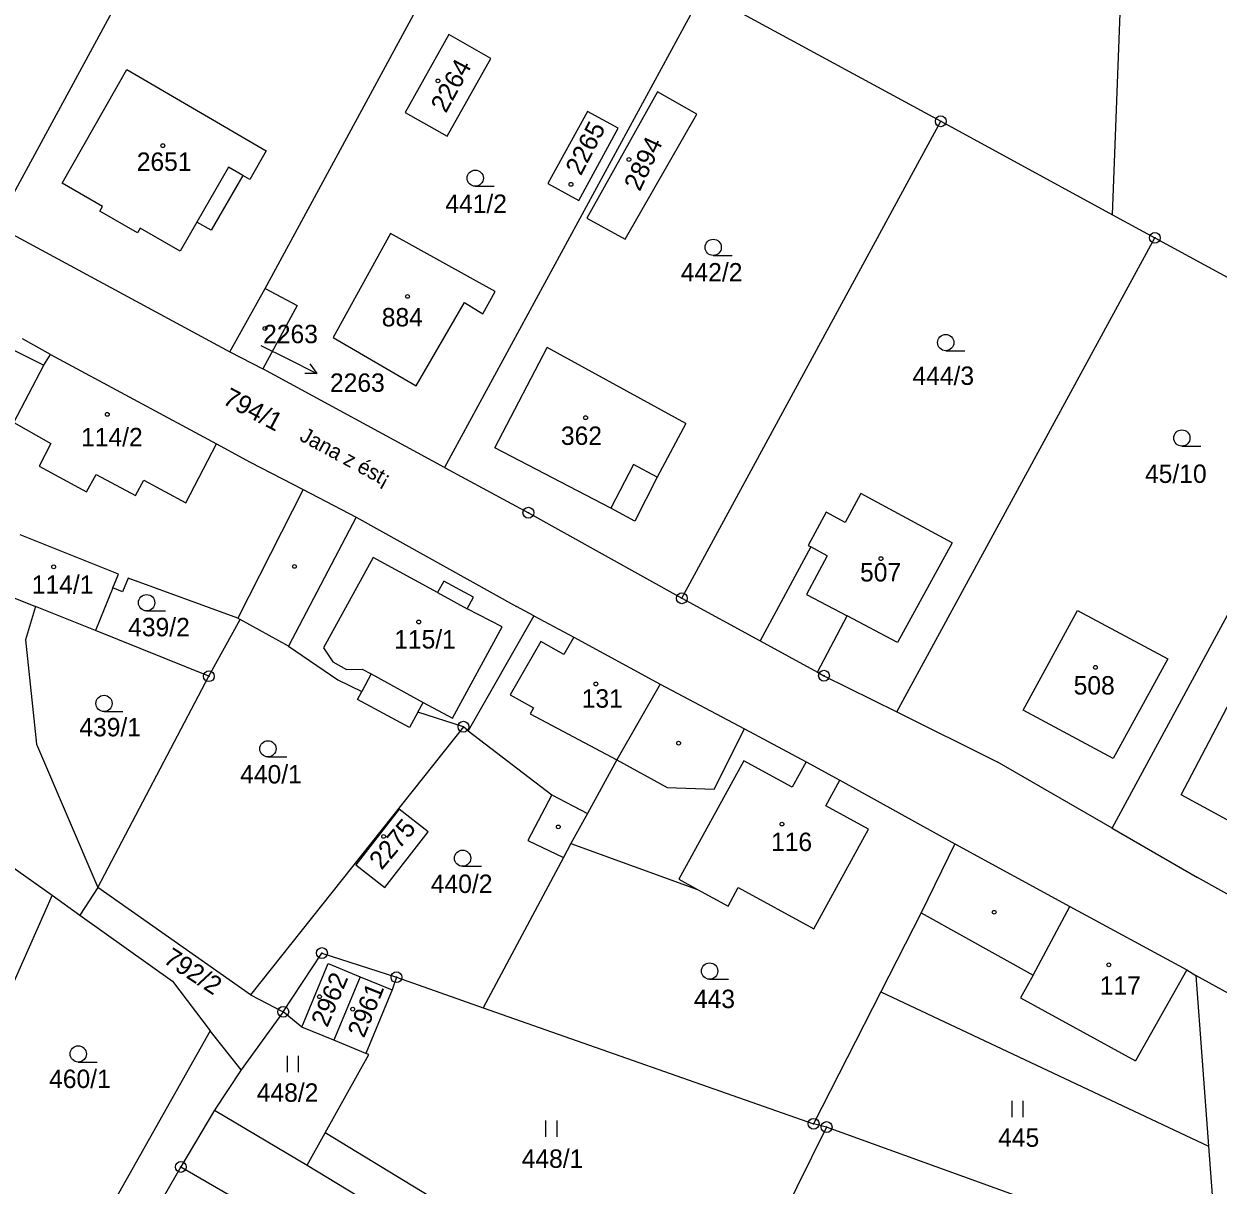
# Model space of a CAD drawing. Extents: x -735249 to -729401, y -1124843 to -1121828.
# Drawn here: x -734647.6 to -734537.4, y -1122716.1 to -1122608.9 of the extents above; entities that cross this region are included whole.
import ezdxf

# ---------------------------------------------------------------- set-up
doc = ezdxf.new("R2010")
doc.units = 0
for name, color, linetype in [('Vrstva 1', 7, 'Continuous'), ('Vrstva 13', 7, 'Continuous'), ('Vrstva 15', 7, 'Continuous'), ('Vrstva 16', 7, 'Continuous'), ('Vrstva 18', 7, 'Continuous'), ('Vrstva 19', 7, 'Continuous'), ('Vrstva 25', 7, 'Continuous'), ('Vrstva 4', 7, 'Continuous')]:
    doc.layers.add(name, color=color, linetype=linetype)

msp = doc.modelspace()

# ---------------------------------------------------------------- linework, layer by layer
at = {"layer": 'Vrstva 1'}
for points in [[(-734626.3, -1122583.45), (-734650.22, -1122627.53)], [(-734625.34, -1122633.34), (-734604.69, -1122595.21)], [(-734584.93, -1122605.96), (-734608.78, -1122649.88)], [(-734584.93, -1122605.96), (-734562.97, -1122617.91)], [(-734608.4, -1122609.91), (-734612.43, -1122617.09)], [(-734604.51, -1122612.1), (-734608.4, -1122609.91)], [(-734644.1, -1122623.62), (-734638.12, -1122613.14)], [(-734638.12, -1122613.14), (-734625.25, -1122620.65)], [(-734608.54, -1122619.28), (-734604.51, -1122612.1)], [(-734589.11, -1122615.2), (-734595.66, -1122626.84)], [(-734585.49, -1122617.24), (-734589.11, -1122615.2)], [(-734612.43, -1122617.09), (-734608.54, -1122619.28)], [(-734595.58, -1122617), (-734599.24, -1122623.66)], [(-734592.74, -1122618.54), (-734595.58, -1122617)], [(-734592.11, -1122628.8), (-734585.49, -1122617.24)], [(-734596.38, -1122625.21), (-734592.74, -1122618.54)], [(-734586.87, -1122661.95), (-734562.97, -1122617.91)], [(-734562.97, -1122617.91), (-734547.12, -1122626.54)], [(-734625.25, -1122620.65), (-734626.77, -1122623.29)], [(-734627.41, -1122622.92), (-734630.32, -1122627.97)], [(-734626.77, -1122623.29), (-734627.41, -1122622.92)], [(-734640.37, -1122625.77), (-734644.1, -1122623.62)], [(-734599.24, -1122623.66), (-734596.38, -1122625.21)], [(-734640.62, -1122626.21), (-734640.37, -1122625.77)], [(-734637.13, -1122628.22), (-734640.62, -1122626.21)], [(-734650.22, -1122627.53), (-734628.62, -1122639.19)], [(-734631.64, -1122627.21), (-734633.19, -1122629.9)], [(-734630.32, -1122627.97), (-734631.64, -1122627.21)], [(-734595.66, -1122626.84), (-734592.11, -1122628.8)], [(-734636.88, -1122627.78), (-734637.13, -1122628.22)], [(-734633.19, -1122629.9), (-734636.88, -1122627.78)], [(-734613.78, -1122628.27), (-734619.08, -1122637.87)], [(-734604.11, -1122633.61), (-734613.78, -1122628.27)], [(-734567.03, -1122672.44), (-734543.2, -1122628.67)], [(-734628.62, -1122639.19), (-734625.34, -1122633.34)], [(-734625.34, -1122633.34), (-734622.39, -1122634.92)], [(-734605.25, -1122635.68), (-734604.11, -1122633.61)], [(-734622.39, -1122634.92), (-734625.56, -1122640.78)], [(-734611.39, -1122642.32), (-734606.93, -1122634.63)], [(-734606.93, -1122634.63), (-734605.25, -1122635.68)], [(-734645.16, -1122639.44), (-734647.76, -1122638.01)], [(-734619.08, -1122637.87), (-734611.39, -1122642.32)], [(-734645.79, -1122640.44), (-734645.16, -1122639.44)], [(-734645.16, -1122639.44), (-734629.85, -1122647.69)], [(-734628.62, -1122639.19), (-734625.56, -1122640.78)], [(-734604.15, -1122648.07), (-734599.32, -1122638.81)], [(-734586.51, -1122645.81), (-734599.32, -1122638.81)], [(-734547.14, -1122683.19), (-734523.44, -1122639.42)], [(-734648.54, -1122645.72), (-734645.79, -1122640.44)], [(-734608.78, -1122649.88), (-734625.56, -1122640.78)], [(-734586.51, -1122645.81), (-734589.14, -1122650.78)], [(-734629.85, -1122647.69), (-734626.73, -1122649.38)], [(-734593.43, -1122653.64), (-734604.15, -1122648.07)], [(-734626.73, -1122649.38), (-734621.83, -1122651.92)], [(-734608.78, -1122649.88), (-734601.04, -1122654.05)], [(-734589.14, -1122650.78), (-734591.2, -1122654.82)], [(-734621.83, -1122651.92), (-734627.86, -1122663.79)], [(-734621.83, -1122651.92), (-734616.93, -1122654.46)], [(-734570.34, -1122652.28), (-734571.79, -1122654.96)], [(-734561.92, -1122656.83), (-734570.34, -1122652.28)], [(-734591.2, -1122654.82), (-734593.43, -1122653.64)], [(-734616.93, -1122654.46), (-734602.14, -1122662.71)], [(-734601.04, -1122654.05), (-734586.87, -1122661.95)], [(-734573.56, -1122654), (-734575.22, -1122657.07)], [(-734571.79, -1122654.96), (-734573.56, -1122654)], [(-734638.9, -1122659.73), (-734647.95, -1122656.08)], [(-734574.98, -1122657.2), (-734579.64, -1122665.89)], [(-734575.22, -1122657.07), (-734574.98, -1122657.2)], [(-734561.92, -1122656.83), (-734566.95, -1122666.03)], [(-734639.42, -1122661), (-734638.9, -1122659.73)], [(-734637.99, -1122660.1), (-734638.5, -1122661.37)], [(-734627.86, -1122663.79), (-734637.99, -1122660.1)], [(-734639.42, -1122661), (-734641, -1122664.93)], [(-734638.5, -1122661.37), (-734639.42, -1122661)], [(-734646.54, -1122662.72), (-734647.48, -1122665.8)], [(-734641, -1122664.93), (-734646.54, -1122662.72)], [(-734600.54, -1122663.56), (-734602.14, -1122662.71)], [(-734586.87, -1122661.95), (-734579.64, -1122665.89)], [(-734630.54, -1122669.15), (-734627.64, -1122663.91)], [(-734627.86, -1122663.79), (-734627.64, -1122663.91)], [(-734623.2, -1122666.38), (-734627.64, -1122663.91)], [(-734600.54, -1122663.56), (-734606.6, -1122674.18)], [(-734600.54, -1122663.56), (-734596.85, -1122665.54)], [(-734574.34, -1122668.78), (-734571.6, -1122663.58)], [(-734566.95, -1122666.03), (-734571.6, -1122663.58)], [(-734555.36, -1122672.29), (-734550.33, -1122663.09)], [(-734550.33, -1122663.09), (-734542.01, -1122667.53)], [(-734630.54, -1122669.15), (-734641, -1122664.93)], [(-734647.48, -1122665.8), (-734646.44, -1122675.42)], [(-734596.85, -1122665.54), (-734588.86, -1122669.87)], [(-734579.64, -1122665.89), (-734574.34, -1122668.78)], [(-734623.2, -1122666.38), (-734618.63, -1122669.48)], [(-734542.01, -1122667.53), (-734547.04, -1122676.73)], [(-734640.8, -1122688.67), (-734630.54, -1122669.15)], [(-734574.34, -1122668.78), (-734573.75, -1122669.1)], [(-734573.75, -1122669.1), (-734567.03, -1122672.44)], [(-734618.63, -1122669.48), (-734616.43, -1122670.56)], [(-734588.86, -1122669.87), (-734592.88, -1122676.88)], [(-734588.86, -1122669.87), (-734581.1, -1122673.99)], [(-734616.83, -1122671.29), (-734616.43, -1122670.56)], [(-734612.02, -1122673.87), (-734616.83, -1122671.29)], [(-734540.77, -1122680.09), (-734535.9, -1122670.83)], [(-734611.26, -1122672.48), (-734612.02, -1122673.87)], [(-734607.04, -1122673.81), (-734611.26, -1122672.48)], [(-734567.03, -1122672.44), (-734557.76, -1122677.05)], [(-734547.04, -1122676.73), (-734555.36, -1122672.29)], [(-734607.04, -1122673.81), (-734626.7, -1122698.56)], [(-734606.6, -1122674.18), (-734607.04, -1122673.81)], [(-734606.6, -1122674.18), (-734598.88, -1122680.1)], [(-734581.1, -1122673.99), (-734575.4, -1122677.06)], [(-734646.44, -1122675.42), (-734640.8, -1122688.67)], [(-734592.88, -1122676.88), (-734595.59, -1122681.81)], [(-734575.4, -1122677.06), (-734572.29, -1122678.75)], [(-734547.14, -1122683.19), (-734557.76, -1122677.05)], [(-734573.57, -1122681.11), (-734572.29, -1122678.75)], [(-734572.29, -1122678.75), (-734561.67, -1122684.62)], [(-734598.88, -1122680.1), (-734601.09, -1122684.33)], [(-734532.4, -1122684.64), (-734540.77, -1122680.09)], [(-734612.98, -1122681.43), (-734616.97, -1122686.56)], [(-734610.3, -1122683.5), (-734612.98, -1122681.43)], [(-734569.64, -1122683.27), (-734573.57, -1122681.11)], [(-734595.59, -1122681.81), (-734597.11, -1122684.6)], [(-734653.82, -1122683.16), (-734645.02, -1122689.37)], [(-734614.3, -1122688.64), (-734610.3, -1122683.5)], [(-734574.69, -1122692.48), (-734569.64, -1122683.27)], [(-734547.14, -1122683.19), (-734539.28, -1122687.73)], [(-734601.09, -1122684.33), (-734597.81, -1122685.87)], [(-734597.11, -1122684.6), (-734597.81, -1122685.87)], [(-734597.11, -1122684.6), (-734585.43, -1122688.83)], [(-734561.67, -1122684.62), (-734564.78, -1122691)], [(-734561.67, -1122684.62), (-734551.05, -1122690.4)], [(-734597.81, -1122685.87), (-734605.23, -1122699.77)], [(-734616.97, -1122686.56), (-734614.3, -1122688.64)], [(-734531.21, -1122692.22), (-734539.28, -1122687.73)], [(-734640.8, -1122688.67), (-734642.46, -1122691.2)], [(-734626.7, -1122698.56), (-734640.8, -1122688.67)], [(-734585.43, -1122688.83), (-734582.6, -1122690.38)], [(-734582.6, -1122690.38), (-734581.66, -1122688.66)], [(-734581.66, -1122688.66), (-734574.69, -1122692.48)], [(-734645.02, -1122689.37), (-734656.36, -1122714.98)], [(-734645.02, -1122689.37), (-734642.46, -1122691.2)], [(-734642.46, -1122691.2), (-734633.89, -1122697.31)], [(-734564.78, -1122691), (-734568.49, -1122698.28)], [(-734551.05, -1122690.4), (-734540.26, -1122696.27)], [(-734623.67, -1122700.13), (-734620.1, -1122694.71)], [(-734620.1, -1122694.71), (-734613.22, -1122696.94)], [(-734616.58, -1122696.89), (-734619, -1122702.76)], [(-734616.58, -1122696.89), (-734613.63, -1122698.11)], [(-734613.22, -1122696.94), (-734613.63, -1122698.11)], [(-734613.22, -1122696.94), (-734605.23, -1122699.77)], [(-734540.26, -1122696.27), (-734539.43, -1122696.77)], [(-734531.09, -1122701.37), (-734539.43, -1122696.77)], [(-734539.43, -1122696.77), (-734538.24, -1122712.53)], [(-734633.89, -1122697.31), (-734630.42, -1122701.9)], [(-734626.7, -1122698.56), (-734623.67, -1122700.13)], [(-734613.63, -1122698.11), (-734616.05, -1122703.98)], [(-734568.49, -1122698.28), (-734574.71, -1122710.47)], [(-734568.49, -1122698.28), (-734538.24, -1122712.53)], [(-734623.67, -1122700.13), (-734627.55, -1122705.48)], [(-734621.95, -1122701.54), (-734623.67, -1122700.13)], [(-734605.23, -1122699.77), (-734574.71, -1122710.47)], [(-734630.42, -1122701.9), (-734642.59, -1122723.45)], [(-734627.55, -1122705.48), (-734630.42, -1122701.9)], [(-734619, -1122702.76), (-734621.95, -1122701.54)], [(-734616.05, -1122703.98), (-734619, -1122702.76)], [(-734619.81, -1122711.3), (-734615.77, -1122704.09)], [(-734615.77, -1122704.09), (-734616.05, -1122703.98)], [(-734627.55, -1122705.48), (-734630.02, -1122709.21)], [(-734630.02, -1122709.21), (-734633.13, -1122714.46)], [(-734630.02, -1122709.21), (-734621.48, -1122714.29)], [(-734621.48, -1122714.29), (-734619.81, -1122711.3)], [(-734588.15, -1122730.56), (-734619.81, -1122711.3)], [(-734573.51, -1122710.77), (-734577.64, -1122719.13)], [(-734573.51, -1122710.77), (-734574.71, -1122710.47)], [(-734552.15, -1122718.52), (-734573.51, -1122710.77)], [(-734538.24, -1122712.53), (-734537.44, -1122723.23)], [(-734633.13, -1122714.46), (-734648.03, -1122740.29)], [(-734633.13, -1122714.46), (-734626.92, -1122718.04)], [(-734621.48, -1122714.29), (-734593.05, -1122731.53)]]:
    msp.add_lwpolyline(points, dxfattribs=at)
at = {"layer": 'Vrstva 13'}
for points in [[(-734547.12, -1122626.54), (-734546.41, -1122607.92)], [(-734547.12, -1122626.54), (-734543.2, -1122628.67)], [(-734543.2, -1122628.67), (-734523.44, -1122639.42)]]:
    msp.add_lwpolyline(points, dxfattribs=at)
at = {"layer": 'Vrstva 16'}
msp.add_lwpolyline([(-734625.73, -1122638.6), (-734623.24, -1122639.85)], dxfattribs=at)
at = {"layer": 'Vrstva 25'}
for points in [[(-734605.95, -1122623.91), (-734604.2, -1122623.91)], [(-734583.98, -1122630.3), (-734582.23, -1122630.3)], [(-734562.51, -1122639.09), (-734560.76, -1122639.09)], [(-734623.24, -1122639.85), (-734620.56, -1122641.197)], [(-734621.229, -1122640.301), (-734620.56, -1122641.197), (-734621.678, -1122641.195)], [(-734540.71, -1122647.9), (-734538.96, -1122647.9)], [(-734636.29, -1122663.11), (-734634.54, -1122663.11)], [(-734640.22, -1122672.41), (-734638.47, -1122672.41)], [(-734625.09, -1122676.6), (-734623.34, -1122676.6)], [(-734607.12, -1122686.7), (-734605.37, -1122686.7)], [(-734584.31, -1122697.12), (-734582.56, -1122697.12)], [(-734623.287, -1122705.695), (-734623.287, -1122704.195)], [(-734622.253, -1122705.695), (-734622.253, -1122704.195)], [(-734642.6, -1122704.77), (-734640.85, -1122704.77)], [(-734556.387, -1122709.865), (-734556.387, -1122708.365)], [(-734555.353, -1122709.865), (-734555.353, -1122708.365)], [(-734599.417, -1122711.665), (-734599.417, -1122710.165)], [(-734598.383, -1122711.665), (-734598.383, -1122710.165)]]:
    msp.add_lwpolyline(points, dxfattribs=at)
for centre, radius in [((-734609.39, -1122614.18), 0.175), ((-734562.97, -1122617.91), 0.5), ((-734562.97, -1122617.91), 0.032), ((-734634.79, -1122620.16), 0.175), ((-734591.76, -1122621.44), 0.175), ((-734605.95, -1122623.16), 0.75), ((-734597.11, -1122623.73), 0.175), ((-734543.2, -1122628.67), 0.5), ((-734583.98, -1122629.55), 0.75), ((-734543.2, -1122628.67), 0.032), ((-734612.2, -1122634.08), 0.175), ((-734625.36, -1122637.04), 0.175), ((-734562.51, -1122638.34), 0.75), ((-734639.92, -1122644.97), 0.175), ((-734595.76, -1122645.28), 0.175), ((-734540.71, -1122647.15), 0.75), ((-734601.04, -1122654.05), 0.5), ((-734601.04, -1122654.05), 0.032), ((-734568.49, -1122658.29), 0.175), ((-734644.87, -1122659.05), 0.175), ((-734622.64, -1122659.01), 0.175), ((-734636.29, -1122662.36), 0.75), ((-734586.87, -1122661.95), 0.5), ((-734586.87, -1122661.95), 0.032), ((-734611.17, -1122664.14), 0.175), ((-734548.69, -1122668.33), 0.175), ((-734630.54, -1122669.15), 0.5), ((-734630.54, -1122669.15), 0.032), ((-734573.75, -1122669.1), 0.5), ((-734573.75, -1122669.1), 0.032), ((-734594.81, -1122669.86), 0.175), ((-734640.22, -1122671.66), 0.75), ((-734607.04, -1122673.81), 0.5), ((-734607.04, -1122673.81), 0.032), ((-734625.09, -1122675.85), 0.75), ((-734587.17, -1122675.33), 0.175), ((-734577.63, -1122682.8), 0.175), ((-734598.28, -1122683.06), 0.175), ((-734614.41, -1122683.94), 0.175), ((-734607.12, -1122685.95), 0.75), ((-734558.04, -1122690.94), 0.175), ((-734620.1, -1122694.71), 0.5), ((-734620.1, -1122694.71), 0.032), ((-734584.31, -1122696.37), 0.75), ((-734547.45, -1122695.8), 0.175), ((-734613.22, -1122696.94), 0.5), ((-734613.22, -1122696.94), 0.032), ((-734620.33, -1122698.74), 0.174), ((-734623.67, -1122700.13), 0.5), ((-734623.67, -1122700.13), 0.032), ((-734617.26, -1122699.89), 0.175), ((-734642.6, -1122704.02), 0.75), ((-734574.71, -1122710.47), 0.5), ((-734574.71, -1122710.47), 0.032), ((-734573.51, -1122710.77), 0.5), ((-734573.51, -1122710.77), 0.032), ((-734633.13, -1122714.46), 0.5), ((-734633.13, -1122714.46), 0.032)]:
    msp.add_circle(centre, radius, dxfattribs=at)
at = {"layer": 'Vrstva 4'}
for points in [[(-734628.74, -1122622.16), (-734631.64, -1122627.21)], [(-734627.41, -1122622.92), (-734628.74, -1122622.16)], [(-734648.91, -1122638.87), (-734645.79, -1122640.44)], [(-734648.54, -1122645.72), (-734645.14, -1122647.66)], [(-734645.14, -1122647.66), (-734646.2, -1122649.76)], [(-734632.68, -1122653.13), (-734629.85, -1122647.69)], [(-734646.2, -1122649.76), (-734641.83, -1122652.13)], [(-734641.83, -1122652.13), (-734640.96, -1122650.51)], [(-734640.96, -1122650.51), (-734637.33, -1122652.47)], [(-734591.35, -1122649.61), (-734593.43, -1122653.64)], [(-734589.14, -1122650.78), (-734591.35, -1122649.61)], [(-734637.33, -1122652.47), (-734636.55, -1122651.03)], [(-734636.55, -1122651.03), (-734632.68, -1122653.13)], [(-734616.93, -1122654.46), (-734623.2, -1122666.38)], [(-734573.45, -1122658.03), (-734574.98, -1122657.2)], [(-734615.37, -1122658.17), (-734619.96, -1122666.54)], [(-734609.42, -1122661.42), (-734615.37, -1122658.17)], [(-734573.45, -1122658.03), (-734575.37, -1122661.59)], [(-734608.84, -1122660.36), (-734609.42, -1122661.42)], [(-734606.1, -1122661.86), (-734608.84, -1122660.36)], [(-734650.02, -1122661.34), (-734646.54, -1122662.72)], [(-734609.42, -1122661.42), (-734606.68, -1122662.92)], [(-734575.37, -1122661.59), (-734571.6, -1122663.58)], [(-734606.68, -1122662.92), (-734606.1, -1122661.86)], [(-734603.46, -1122664.58), (-734606.68, -1122662.92)], [(-734608.04, -1122673.03), (-734603.46, -1122664.58)], [(-734599.9, -1122665.94), (-734602.71, -1122670.86)], [(-734597.77, -1122667.15), (-734599.9, -1122665.94)], [(-734596.85, -1122665.54), (-734597.77, -1122667.15)], [(-734619.96, -1122666.54), (-734619.11, -1122667.83)], [(-734619.11, -1122667.83), (-734617.83, -1122668.54)], [(-734617.83, -1122668.54), (-734616.38, -1122668.49)], [(-734615.55, -1122668.94), (-734616.43, -1122670.56)], [(-734616.38, -1122668.49), (-734615.55, -1122668.94)], [(-734615.55, -1122668.94), (-734610.75, -1122671.56)], [(-734611.26, -1122672.48), (-734610.75, -1122671.56)], [(-734610.75, -1122671.56), (-734608.04, -1122673.03)], [(-734602.71, -1122670.86), (-734600.57, -1122672.07)], [(-734600.57, -1122672.07), (-734600.89, -1122672.63)], [(-734600.89, -1122672.63), (-734592.88, -1122676.88)], [(-734583.88, -1122679.59), (-734581.1, -1122673.99)], [(-734592.88, -1122676.88), (-734588.22, -1122679.41)], [(-734581.15, -1122676.95), (-734587.15, -1122687.89)], [(-734576.7, -1122679.4), (-734581.15, -1122676.95)], [(-734575.4, -1122677.06), (-734576.7, -1122679.4)], [(-734598.88, -1122680.1), (-734595.59, -1122681.81)], [(-734588.22, -1122679.41), (-734583.88, -1122679.59)], [(-734587.15, -1122687.89), (-734585.43, -1122688.83)], [(-734564.78, -1122691), (-734554.44, -1122696.76)], [(-734554.44, -1122696.76), (-734551.05, -1122690.4)], [(-734621.95, -1122701.54), (-734619.54, -1122695.68)], [(-734619.54, -1122695.68), (-734616.58, -1122696.89)], [(-734554.44, -1122696.76), (-734555.6, -1122698.84)], [(-734540.26, -1122696.27), (-734545, -1122704.66)], [(-734555.6, -1122698.84), (-734545, -1122704.66)]]:
    msp.add_lwpolyline(points, dxfattribs=at)

# ---------------------------------------------------------------- texts
at = {"layer": 'Vrstva 15'}
msp.add_text('Jana z ést¡', height=1.39999, rotation=331.50264, dxfattribs=at).set_placement((-734622.269, -1122647.32))
at = {"layer": 'Vrstva 16'}
msp.add_text('2263', height=1.7, dxfattribs=at).set_placement((-734619.36, -1122642.89))
at = {"layer": 'Vrstva 18'}
for s, p in [('441/2', (-734608.71, -1122626.37)), ('442/2', (-734586.97, -1122632.7)), ('444/3', (-734565.58, -1122642.25)), ('45/10', (-734544.11, -1122651.3)), ('439/2', (-734637.99, -1122665.46)), ('439/1', (-734642.5, -1122674.7)), ('440/1', (-734627.65, -1122679.05)), ('440/2', (-734610.05, -1122689.16)), ('443', (-734585.76, -1122699.79)), ('460/1', (-734645.29, -1122707.17)), ('448/2', (-734626.12, -1122708.44)), ('445', (-734557.67, -1122712.6)), ('448/1', (-734601.66, -1122714.54))]:
    msp.add_text(s, height=1.7, dxfattribs=at).set_placement(p)
for s, rotation, p in [('794/1', 332.20264, (-734629.37, -1122643.937)), ('792/2', 326.9026, (-734634.844, -1122695.542))]:
    msp.add_text(s, height=1.7, rotation=rotation, dxfattribs=at).set_placement(p)
at = {"layer": 'Vrstva 19'}
for s, rotation, p in [('2264', 61.40049, (-734608.659, -1122617.229)), ('2265', 62.7005, (-734596.195, -1122623.011)), ('2894', 64.80052, (-734590.755, -1122624.454)), ('2275', 49.8004, (-734614.593, -1122687.109)), ('2962', 67.10053, (-734619.606, -1122701.638)), ('2961', 68.00054, (-734616.22, -1122702.62))]:
    msp.add_text(s, height=1.7, rotation=rotation, dxfattribs=at).set_placement(p)
for s, p in [('2651', (-734637.2, -1122622.49)), ('884', (-734614.58, -1122636.85)), ('2263', (-734625.53, -1122638.4)), ('114/2', (-734642.34, -1122647.92)), ('362', (-734598.04, -1122647.79)), ('507', (-734570.42, -1122660.4)), ('114/1', (-734646.89, -1122661.54)), ('115/1', (-734613.43, -1122666.59)), ('508', (-734550.7, -1122670.84)), ('131', (-734596.12, -1122672.05)), ('116', (-734578.64, -1122685.29)), ('117', (-734548.29, -1122698.55))]:
    msp.add_text(s, height=1.7, dxfattribs=at).set_placement(p)

doc.saveas('drawing.dxf')
